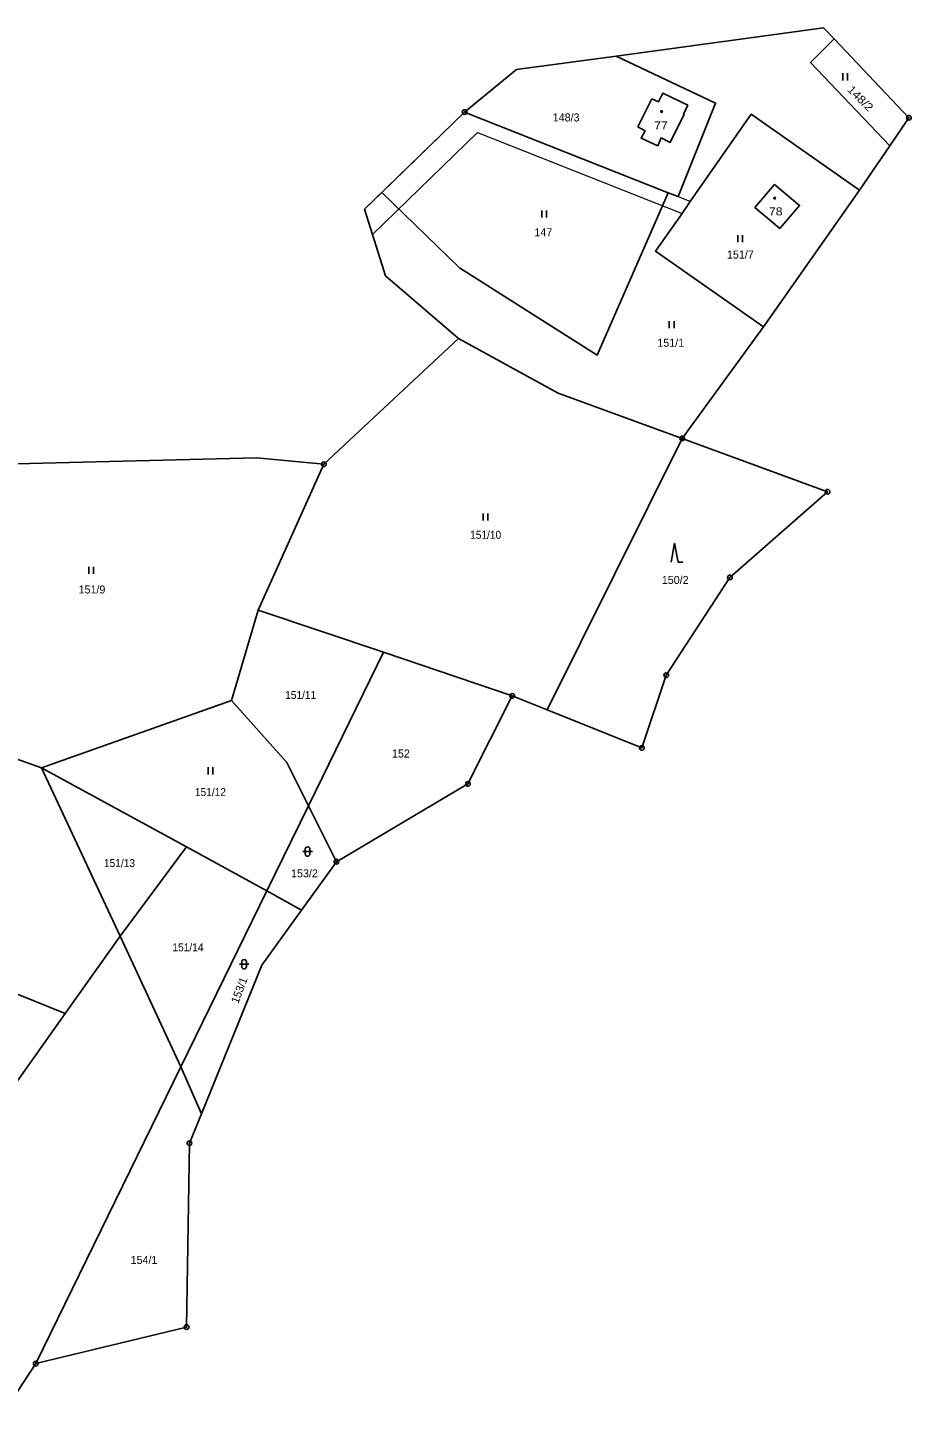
# Model space of a CAD drawing. Extents: x -632162 to -629607, y -1101195 to -1098670.
# Drawn here: x -631672.5 to -631484.8, y -1099500.1 to -1099205.6 of the extents above; entities that cross this region are included whole.
import ezdxf
from ezdxf.enums import TextEntityAlignment as Align

# ---------------------------------------------------------------- set-up
doc = ezdxf.new("R2010")
doc.units = 0
doc.header["$LTSCALE"] = 0.68
for name, color, linetype, lineweight in [('1', 7, 'Continuous', 25), ('13', 7, 'Continuous', 13), ('3', 7, 'Continuous', 25), ('5', 7, 'Continuous', 25), ('8', 7, 'Continuous', 25)]:
    doc.layers.add(name, color=color, linetype=linetype, lineweight=lineweight)
doc.layers.add('2', color=7, linetype='Continuous')

msp = doc.modelspace()

# ---------------------------------------------------------------- linework, layer by layer
at = {"layer": '1'}
for p, q in [((-631597.31, -1099240.59), (-631579.7, -1099223.49)), ((-631495.85, -1099240.05), (-631489.4, -1099230.63)), ((-631516.2, -1099269.09), (-631495.85, -1099240.05)), ((-631533.48, -1099292.81), (-631562.16, -1099350.47)), ((-631623.59, -1099329.29), (-631609.58, -1099298.27)), ((-631629.19, -1099348.46), (-631623.59, -1099329.29)), ((-631623.59, -1099329.29), (-631596.93, -1099338.22)), ((-631562.16, -1099350.47), (-631569.59, -1099347.49)), ((-631612.87, -1099370.83), (-631621.71, -1099388.91)), ((-631614.33, -1099392.99), (-631606.93, -1099382.71)), ((-631652.89, -1099398.51), (-631639.98, -1099426.29)), ((-631639.98, -1099426.29), (-631670.8, -1099489.34)), ((-631670.8, -1099489.34), (-631686.1, -1099512.39))]:
    msp.add_line(p, q, dxfattribs=at)
for points in [[(-631501.23, -1099207.89), (-631503.44, -1099205.56), (-631547.49, -1099211.57)], [(-631501.23, -1099207.89), (-631506.25, -1099212.98), (-631489.4, -1099230.63)], [(-631489.4, -1099230.63), (-631485.33, -1099224.67), (-631501.23, -1099207.89)], [(-631547.49, -1099211.57), (-631568.66, -1099214.41), (-631579.7, -1099223.49), (-631536.47, -1099240.6)], [(-631536.47, -1099240.6), (-631534.37, -1099241.43), (-631526.38, -1099221.56), (-631547.49, -1099211.57)], [(-631532.28, -1099222.01), (-631533.19, -1099223.89), (-631533.1, -1099223.93), (-631536.01, -1099229.91), (-631537.98, -1099228.97), (-631538.65, -1099230.63), (-631542.21, -1099229.01), (-631541.36, -1099227.45), (-631542.91, -1099226.63), (-631539.92, -1099220.68)], [(-631539.92, -1099220.68), (-631538.5, -1099221.3), (-631537.59, -1099219.43), (-631532.28, -1099222.01)], [(-631516.2, -1099269.09), (-631539.14, -1099253.01), (-631533.53, -1099244.99), (-631531.76, -1099242.46), (-631518.82, -1099223.95), (-631495.85, -1099240.05)], [(-631597.31, -1099240.59), (-631600.96, -1099244.13), (-631599.28, -1099249.47), (-631596.52, -1099258.28), (-631580.97, -1099271.56)], [(-631536.47, -1099240.6), (-631551.52, -1099275.08), (-631580.76, -1099256.57), (-631597.31, -1099240.59)], [(-631580.97, -1099271.56), (-631559.84, -1099283.19), (-631533.48, -1099292.81), (-631516.2, -1099269.09)], [(-631718.05, -1099324.49), (-631708.37, -1099313.64), (-631684.97, -1099304.46), (-631674.98, -1099298.2), (-631623.89, -1099296.9), (-631609.58, -1099298.27), (-631580.97, -1099271.56)], [(-631562.16, -1099350.47), (-631542.06, -1099358.54), (-631536.88, -1099343.12), (-631523.34, -1099322.33), (-631502.6, -1099304.14), (-631533.48, -1099292.81)], [(-631731.43, -1099349.31), (-631712.34, -1099353.88), (-631678.46, -1099359.68), (-631669.56, -1099362.76), (-631629.19, -1099348.46)], [(-631629.19, -1099348.46), (-631617.44, -1099361.63), (-631612.87, -1099370.83)], [(-631669.56, -1099362.76), (-631638.78, -1099379.58), (-631621.71, -1099388.91)], [(-631669.56, -1099362.76), (-631652.89, -1099398.51), (-631638.78, -1099379.58)], [(-631737.97, -1099385.26), (-631664.56, -1099414.97), (-631652.89, -1099398.51)], [(-631614.33, -1099392.99), (-631621.71, -1099388.91), (-631639.98, -1099426.29), (-631635.62, -1099436.29)], [(-631635.62, -1099436.29), (-631622.77, -1099404.7), (-631614.33, -1099392.99)], [(-631721.04, -1099494.62), (-631697.69, -1099461.69), (-631664.56, -1099414.97)], [(-631670.8, -1099489.34), (-631638.75, -1099481.56), (-631638.16, -1099442.52), (-631635.62, -1099436.29)]]:
    msp.add_lwpolyline(points, dxfattribs=at)
for points in [[(-631518.08, -1099243.73), (-631513.88, -1099238.85), (-631508.55, -1099243.32), (-631512.77, -1099248.18)], [(-631606.93, -1099382.71), (-631579, -1099366.2), (-631569.59, -1099347.49), (-631596.93, -1099338.22), (-631612.87, -1099370.83)]]:
    msp.add_lwpolyline(points, close=True, dxfattribs=at)
at = {"layer": '13'}
msp.add_lwpolyline([(-631576.96, -1099227.8), (-631533.53, -1099244.99), (-631531.76, -1099242.46), (-631579.7, -1099223.49), (-631600.96, -1099244.13), (-631599.28, -1099249.47)], close=True, dxfattribs=at)
at = {"layer": '3'}
for p, q in [((-631499.371, -1099216.74), (-631499.371, -1099215.24)), ((-631498.37, -1099216.74), (-631498.37, -1099215.24)), ((-631563.291, -1099245.89), (-631563.291, -1099244.39)), ((-631562.29, -1099245.89), (-631562.29, -1099244.39)), ((-631521.661, -1099251.11), (-631521.661, -1099249.61)), ((-631520.66, -1099251.11), (-631520.66, -1099249.61)), ((-631536.221, -1099269.36), (-631536.221, -1099267.86)), ((-631535.22, -1099269.36), (-631535.22, -1099267.86)), ((-631575.771, -1099310.23), (-631575.771, -1099308.73)), ((-631574.77, -1099310.23), (-631574.77, -1099308.73)), ((-631659.551, -1099321.56), (-631659.551, -1099320.06)), ((-631658.55, -1099321.56), (-631658.55, -1099320.06)), ((-631534.35, -1099319.08), (-631533.354, -1099319.08)), ((-631634.171, -1099364.16), (-631634.171, -1099362.66)), ((-631633.17, -1099364.16), (-631633.17, -1099362.66)), ((-631614.051, -1099380.561), (-631612.049, -1099380.561)), ((-631613.551, -1099380.061), (-631613.551, -1099381.062)), ((-631612.549, -1099381.062), (-631612.549, -1099380.061)), ((-631627.541, -1099404.501), (-631625.539, -1099404.501)), ((-631627.041, -1099404.001), (-631627.041, -1099405.002)), ((-631626.039, -1099405.002), (-631626.039, -1099404.001))]:
    msp.add_line(p, q, dxfattribs=at)
msp.add_lwpolyline([(-631534.35, -1099319.08), (-631535.1, -1099315.08), (-631535.85, -1099319.08)], dxfattribs=at)
for centre, start, end in [((-631613.05, -1099380.0609), 0, 180), ((-631613.05, -1099381.0609), 180, 359.98789), ((-631626.54, -1099404.0009), 0, 180), ((-631626.54, -1099405.0009), 180, 359.98789)]:
    msp.add_arc(centre, 0.5, start, end, dxfattribs=at)
at = {"layer": '5'}
for centre in [(-631537.8768, -1099223.3692), (-631513.8468, -1099241.7592)]:
    msp.add_circle(centre, 0.175, dxfattribs=at)
at = {"layer": '8'}
for centre, radius in [((-631579.7, -1099223.4899), 0.5), ((-631579.7, -1099223.4899), 0.0303), ((-631485.33, -1099224.6699), 0.5), ((-631485.33, -1099224.6699), 0.0303), ((-631533.48, -1099292.8099), 0.5), ((-631533.48, -1099292.8099), 0.0303), ((-631609.58, -1099298.2699), 0.5), ((-631609.58, -1099298.2699), 0.0303), ((-631502.6, -1099304.1399), 0.5), ((-631502.6, -1099304.1399), 0.0303), ((-631523.34, -1099322.3299), 0.5), ((-631523.34, -1099322.3299), 0.0303), ((-631536.88, -1099343.1199), 0.5), ((-631536.88, -1099343.1199), 0.0303), ((-631569.59, -1099347.4899), 0.5), ((-631569.59, -1099347.4899), 0.0303), ((-631542.06, -1099358.5399), 0.5), ((-631542.06, -1099358.5399), 0.0303), ((-631579, -1099366.1999), 0.5), ((-631579, -1099366.1999), 0.0303), ((-631606.93, -1099382.7099), 0.5), ((-631606.93, -1099382.7099), 0.0303), ((-631638.16, -1099442.5199), 0.5), ((-631638.16, -1099442.5199), 0.0303), ((-631638.75, -1099481.5599), 0.5), ((-631638.75, -1099481.5599), 0.0303), ((-631670.8, -1099489.3399), 0.5), ((-631670.8, -1099489.3399), 0.0303)]:
    msp.add_circle(centre, radius, dxfattribs=at)

# ---------------------------------------------------------------- texts
at = {"layer": '2', "width": 1.15}
msp.add_text('148/2', height=1.7, rotation=315, dxfattribs=at).set_placement((-631496.23, -1099221.161), align=Align.CENTER)
at = {"layer": '2'}
for s, p in [('148/3', (-631558.14, -1099225.47)), ('147', (-631562.989, -1099249.86)), ('151/7', (-631521.13, -1099254.59)), ('151/1', (-631535.92, -1099273.33)), ('151/9', (-631658.86, -1099325.74)), ('150/2', (-631534.97, -1099323.71)), ('152', (-631593.239, -1099360.58)), ('153/2', (-631613.73, -1099386.04)), ('154/1', (-631647.81, -1099468.16))]:
    msp.add_text(s, height=1.7, dxfattribs=at).set_placement(p, align=Align.CENTER)
for s, width, p in [('77', 1.15, (-631537.99, -1099227.15)), ('78', 1.15, (-631513.62, -1099245.43)), ('151/10', 0.95, (-631575.239, -1099314.12)), ('151/11', 0.95, (-631614.529, -1099348.15)), ('151/12', 0.95, (-631633.699, -1099368.77)), ('151/13', 0.95, (-631653.019, -1099383.86)), ('151/14', 0.95, (-631638.479, -1099401.76))]:
    msp.add_text(s, height=1.7, dxfattribs=dict(at, width=width)).set_placement(p, align=Align.CENTER)
msp.add_text('153/1', height=1.7, rotation=69, dxfattribs=at).set_placement((-631626.7881, -1099410.3206), align=Align.CENTER)

doc.saveas('drawing.dxf')
